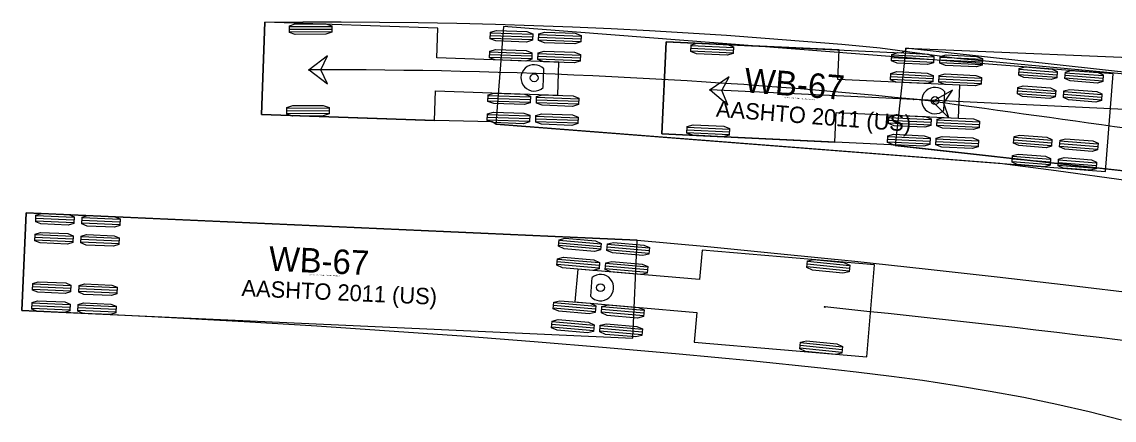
# Model space of a CAD drawing. Extents: x 2175591 to 2194071, y 76570 to 86955.
# Drawn here: x 2176268.4 to 2176363, y 77384.6 to 77419.1 of the extents above; entities that cross this region are included whole.
import ezdxf

# ---------------------------------------------------------------- set-up
doc = ezdxf.new("R2010")
doc.units = 0
doc.layers.add('C-UTIL-STRM-TEXT', color=7, linetype='Continuous')

msp = doc.modelspace()

# ---------------------------------------------------------------- linework, layer by layer
at = {"layer": 'C-UTIL-STRM-TEXT'}
for p, q in [((2176289.42, 77419.093), (2176289.135, 77411.098)), ((2176304.411, 77418.559), (2176289.42, 77419.093)), ((2176291.55, 77418.717), (2176295.216, 77418.727)), ((2176310.102, 77418.729), (2176309.442, 77410.254)), ((2176362.942, 77414.618), (2176310.102, 77418.729)), ((2176291.55, 77418.488), (2176295.217, 77418.498)), ((2176291.551, 77418.258), (2176295.218, 77418.269)), ((2176304.319, 77415.994), (2176304.411, 77418.559)), ((2176308.95, 77417.709), (2176312.614, 77417.579)), ((2176308.958, 77417.938), (2176312.623, 77417.808)), ((2176308.966, 77418.167), (2176312.631, 77418.037)), ((2176313.156, 77417.789), (2176316.82, 77417.658)), ((2176313.164, 77418.018), (2176316.828, 77417.887)), ((2176313.147, 77417.56), (2176316.812, 77417.429)), ((2176324.208, 77417.4), (2176323.829, 77409.409)), ((2176339.191, 77416.69), (2176324.208, 77417.4)), ((2176326.35, 77416.839), (2176330.013, 77416.666)), ((2176326.361, 77417.068), (2176330.024, 77416.895)), ((2176344.981, 77416.848), (2176344.04, 77408.4)), ((2176397.655, 77410.98), (2176344.981, 77416.848)), ((2176314.913, 77415.616), (2176304.319, 77415.994)), ((2176308.891, 77416.06), (2176312.556, 77415.93)), ((2176308.899, 77416.289), (2176312.564, 77416.159)), ((2176308.908, 77416.518), (2176312.572, 77416.388)), ((2176313.089, 77415.911), (2176316.753, 77415.78)), ((2176313.097, 77416.14), (2176316.761, 77416.009)), ((2176313.105, 77416.369), (2176316.769, 77416.238)), ((2176326.34, 77416.611), (2176330.002, 77416.437)), ((2176339.07, 77414.126), (2176339.191, 77416.69)), ((2176343.72, 77415.787), (2176347.383, 77415.613)), ((2176343.731, 77416.016), (2176347.393, 77415.842)), ((2176343.742, 77416.245), (2176347.404, 77416.071)), ((2176347.926, 77415.817), (2176351.589, 77415.643)), ((2176347.937, 77416.046), (2176351.6, 77415.872)), ((2176313.542, 77413.422), (2176313.599, 77415.038)), ((2176314.81, 77412.751), (2176314.913, 77415.616)), ((2176347.915, 77415.588), (2176351.578, 77415.415)), ((2176354.799, 77415.021), (2176358.089, 77414.765)), ((2176349.658, 77413.624), (2176339.07, 77414.126)), ((2176343.642, 77414.139), (2176347.305, 77413.965)), ((2176343.653, 77414.368), (2176347.315, 77414.194)), ((2176343.664, 77414.597), (2176347.326, 77414.423)), ((2176347.837, 77413.94), (2176351.5, 77413.766)), ((2176347.848, 77414.169), (2176351.511, 77413.995)), ((2176347.859, 77414.398), (2176351.522, 77414.224)), ((2176354.763, 77414.564), (2176358.053, 77414.308)), ((2176354.781, 77414.793), (2176358.071, 77414.537)), ((2176358.751, 77414.254), (2176362.041, 77413.998)), ((2176358.769, 77414.483), (2176362.059, 77414.227)), ((2176358.787, 77414.711), (2176362.077, 77414.455)), ((2176362.283, 77406.143), (2176362.942, 77414.618)), ((2176304.126, 77410.564), (2176304.217, 77413.129)), ((2176304.217, 77413.129), (2176314.81, 77412.751)), ((2176404.759, 77409.577), (2176328.014, 77413.215)), ((2176348.261, 77411.446), (2176348.338, 77413.061)), ((2176349.522, 77410.761), (2176349.658, 77413.624)), ((2176354.653, 77413.148), (2176357.943, 77412.892)), ((2176354.671, 77413.376), (2176357.961, 77413.12)), ((2176358.659, 77413.066), (2176361.949, 77412.81)), ((2176308.756, 77412.279), (2176312.421, 77412.149)), ((2176308.765, 77412.508), (2176312.429, 77412.378)), ((2176308.773, 77412.737), (2176312.437, 77412.607)), ((2176312.954, 77412.13), (2176316.618, 77411.999)), ((2176312.962, 77412.359), (2176316.626, 77412.228)), ((2176312.97, 77412.588), (2176316.634, 77412.457)), ((2176354.635, 77412.919), (2176357.925, 77412.663)), ((2176358.623, 77412.609), (2176361.913, 77412.353)), ((2176358.641, 77412.838), (2176361.931, 77412.582)), ((2176289.135, 77411.098), (2176304.126, 77410.564)), ((2176289.135, 77411.098), (2176289.135, 77411.098)), ((2176291.333, 77411.636), (2176295, 77411.649)), ((2176291.334, 77411.407), (2176295, 77411.42)), ((2176291.334, 77411.178), (2176295.001, 77411.191)), ((2176308.714, 77411.088), (2176312.378, 77410.958)), ((2176338.812, 77408.699), (2176338.934, 77411.263)), ((2176338.934, 77411.263), (2176349.522, 77410.761)), ((2176308.698, 77410.63), (2176312.362, 77410.5)), ((2176308.706, 77410.859), (2176312.37, 77410.729)), ((2176309.442, 77410.254), (2176362.283, 77406.143)), ((2176309.442, 77410.254), (2176309.442, 77410.254)), ((2176312.895, 77410.481), (2176316.559, 77410.35)), ((2176312.903, 77410.71), (2176316.568, 77410.579)), ((2176312.911, 77410.939), (2176316.576, 77410.808)), ((2176343.463, 77410.36), (2176347.125, 77410.186)), ((2176343.474, 77410.589), (2176347.136, 77410.415)), ((2176343.485, 77410.817), (2176347.147, 77410.644)), ((2176347.658, 77410.161), (2176351.321, 77409.987)), ((2176347.669, 77410.39), (2176351.332, 77410.216)), ((2176347.68, 77410.619), (2176351.342, 77410.445)), ((2176323.829, 77409.409), (2176338.812, 77408.699)), ((2176323.829, 77409.409), (2176323.829, 77409.409)), ((2176326.004, 77409.535), (2176329.667, 77409.362)), ((2176326.015, 77409.764), (2176329.678, 77409.59)), ((2176326.026, 77409.993), (2176329.689, 77409.819)), ((2176343.407, 77409.169), (2176347.069, 77408.996)), ((2176343.385, 77408.712), (2176347.047, 77408.538)), ((2176343.396, 77408.94), (2176347.058, 77408.767)), ((2176344.04, 77408.4), (2176396.714, 77402.532)), ((2176344.04, 77408.4), (2176344.04, 77408.4)), ((2176347.58, 77408.513), (2176351.243, 77408.339)), ((2176347.591, 77408.742), (2176351.254, 77408.568)), ((2176347.602, 77408.971), (2176351.264, 77408.797)), ((2176354.303, 77408.649), (2176357.593, 77408.393)), ((2176354.321, 77408.877), (2176357.611, 77408.621)), ((2176354.338, 77409.106), (2176357.629, 77408.85)), ((2176358.291, 77408.339), (2176361.581, 77408.083)), ((2176358.309, 77408.567), (2176361.599, 77408.311)), ((2176358.326, 77408.796), (2176361.616, 77408.54)), ((2176354.21, 77407.461), (2176357.501, 77407.205)), ((2176354.175, 77407.004), (2176357.465, 77406.748)), ((2176354.193, 77407.232), (2176357.483, 77406.976)), ((2176358.163, 77406.694), (2176361.453, 77406.438)), ((2176358.181, 77406.922), (2176361.471, 77406.666)), ((2176358.198, 77407.151), (2176361.488, 77406.895)), ((2176268.752, 77402.569), (2176268.369, 77394.078)), ((2176321.698, 77400.183), (2176268.752, 77402.569)), ((2176272.867, 77401.695), (2176269.57, 77401.844)), ((2176272.877, 77401.924), (2176269.58, 77402.073)), ((2176272.887, 77402.153), (2176269.591, 77402.302)), ((2176276.863, 77401.515), (2176273.566, 77401.664)), ((2176276.873, 77401.744), (2176273.576, 77401.893)), ((2176276.883, 77401.973), (2176273.587, 77402.122)), ((2176272.813, 77400.505), (2176269.516, 77400.654)), ((2176272.792, 77400.047), (2176269.496, 77400.196)), ((2176272.803, 77400.276), (2176269.506, 77400.425)), ((2176276.788, 77399.867), (2176273.492, 77400.016)), ((2176276.799, 77400.096), (2176273.502, 77400.244)), ((2176276.809, 77400.325), (2176273.512, 77400.473)), ((2176318.529, 77399.395), (2176314.876, 77399.711)), ((2176318.549, 77399.623), (2176314.896, 77399.939)), ((2176318.569, 77399.852), (2176314.916, 77400.167)), ((2176322.753, 77399.49), (2176319.1, 77399.806)), ((2176321.315, 77391.691), (2176321.698, 77400.183)), ((2176321.698, 77400.183), (2176321.698, 77400.183)), ((2176322.714, 77399.034), (2176319.061, 77399.349)), ((2176322.733, 77399.262), (2176319.08, 77399.577)), ((2176327.323, 77399.325), (2176327.102, 77396.768)), ((2176342.267, 77398.034), (2176327.323, 77399.325)), ((2176318.387, 77397.751), (2176314.734, 77398.067)), ((2176318.407, 77397.98), (2176314.754, 77398.295)), ((2176318.427, 77398.208), (2176314.774, 77398.524)), ((2176322.591, 77397.618), (2176318.938, 77397.934)), ((2176322.611, 77397.846), (2176318.958, 77398.162)), ((2176340.05, 77397.507), (2176336.402, 77397.879)), ((2176340.073, 77397.735), (2176336.426, 77398.107)), ((2176340.097, 77397.963), (2176336.449, 77398.335)), ((2176341.578, 77390.064), (2176342.267, 77398.034)), ((2176342.267, 77398.034), (2176342.267, 77398.034)), ((2176316.541, 77397.681), (2176316.294, 77394.825)), ((2176327.102, 77396.768), (2176316.541, 77397.681)), ((2176317.774, 77396.947), (2176317.635, 77395.336)), ((2176322.572, 77397.39), (2176318.919, 77397.705)), ((2176272.6, 77395.768), (2176269.303, 77395.917)), ((2176272.61, 77395.997), (2176269.313, 77396.146)), ((2176272.62, 77396.226), (2176269.324, 77396.375)), ((2176276.606, 77395.817), (2176273.309, 77395.965)), ((2176276.616, 77396.046), (2176273.319, 77396.194)), ((2176276.595, 77395.588), (2176273.299, 77395.737)), ((2176268.369, 77394.078), (2176321.315, 77391.691)), ((2176272.525, 77394.12), (2176269.229, 77394.268)), ((2176272.536, 77394.349), (2176269.239, 77394.497)), ((2176272.546, 77394.578), (2176269.249, 77394.726)), ((2176276.521, 77393.94), (2176273.225, 77394.088)), ((2176276.532, 77394.169), (2176273.235, 77394.317)), ((2176276.542, 77394.397), (2176273.245, 77394.546)), ((2176318.062, 77393.982), (2176314.408, 77394.298)), ((2176318.081, 77394.21), (2176314.428, 77394.526)), ((2176318.101, 77394.439), (2176314.448, 77394.754)), ((2176316.294, 77394.825), (2176326.855, 77393.912)), ((2176322.266, 77393.849), (2176318.613, 77394.164)), ((2176322.285, 77394.077), (2176318.632, 77394.393)), ((2176317.959, 77392.795), (2176314.306, 77393.11)), ((2176322.246, 77393.62), (2176318.593, 77393.936)), ((2176326.855, 77393.912), (2176326.634, 77391.355)), ((2176317.92, 77392.338), (2176314.266, 77392.654)), ((2176317.939, 77392.566), (2176314.286, 77392.882)), ((2176322.104, 77391.976), (2176318.451, 77392.292)), ((2176322.124, 77392.205), (2176318.471, 77392.52)), ((2176322.143, 77392.433), (2176318.49, 77392.749)), ((2176326.634, 77391.355), (2176341.578, 77390.064)), ((2176339.472, 77390.907), (2176335.825, 77391.28)), ((2176339.426, 77390.451), (2176335.778, 77390.824)), ((2176339.449, 77390.679), (2176335.802, 77391.052))]:
    msp.add_line(p, q, dxfattribs=at)
for points in [[(2176364.273, 77405.327), (2176358.005, 77406.213), (2176353.107, 77406.848), (2176309.442, 77410.254), (2176309.113, 77410.447), (2176304.162, 77410.563), (2176289.135, 77411.098), (2176289.42, 77419.093), (2176292.71, 77419.118), (2176296.036, 77419.121), (2176299.374, 77419.102), (2176302.716, 77419.062), (2176306.059, 77419), (2176309.403, 77418.915), (2176312.746, 77418.809), (2176316.087, 77418.681), (2176319.427, 77418.532), (2176322.766, 77418.36), (2176326.103, 77418.167), (2176329.438, 77417.952), (2176332.771, 77417.715), (2176336.101, 77417.456), (2176339.429, 77417.176), (2176342.753, 77416.87), (2176349.375, 77415.982), (2176388.741, 77412.312)], [(2176396.245, 77402.573), (2176344.068, 77408.397), (2176343.683, 77408.468), (2176323.829, 77409.409), (2176324.208, 77417.4), (2176344.556, 77416.436), (2176344.959, 77416.646), (2176344.981, 77416.848), (2176369.887, 77415.788)], [(2176347.273, 77412.211), (2176346.943, 77412.256), (2176346.612, 77412.298), (2176346.281, 77412.338), (2176345.95, 77412.375), (2176345.619, 77412.41)], [(2176363.653, 77384.577), (2176360.865, 77385.291), (2176358.039, 77385.943), (2176355.18, 77386.537), (2176352.289, 77387.077), (2176349.364, 77387.567), (2176346.421, 77388.009), (2176343.716, 77388.376), (2176340.661, 77388.752), (2176337.615, 77389.094), (2176331.52, 77389.71), (2176325.313, 77390.291), (2176319.039, 77390.845), (2176312.762, 77391.365), (2176306.482, 77391.852), (2176300.201, 77392.305), (2176293.917, 77392.724), (2176287.631, 77393.109), (2176281.343, 77393.459), (2176275.049, 77393.774), (2176268.369, 77394.078), (2176268.752, 77402.569), (2176268.765, 77402.568), (2176268.765, 77402.568)], [(2176268.765, 77402.568), (2176321.698, 77400.183), (2176327.788, 77399.625), (2176334.149, 77399.011), (2176340.559, 77398.36), (2176346.64, 77397.711), (2176352.869, 77397.016), (2176359.09, 77396.29), (2176365.35, 77395.528)]]:
    msp.add_lwpolyline(points, dxfattribs=at)
for points in [[(2176291.551, 77418.202), (2176291.55, 77418.774), (2176292.062, 77418.947), (2176294.702, 77418.955), (2176295.216, 77418.784), (2176295.218, 77418.212), (2176294.705, 77418.038), (2176292.065, 77418.031)], [(2176308.948, 77417.652), (2176308.968, 77418.224), (2176309.488, 77418.378), (2176312.126, 77418.284), (2176312.633, 77418.093), (2176312.612, 77417.522), (2176312.093, 77417.368), (2176309.455, 77417.462)], [(2176313.145, 77417.503), (2176313.166, 77418.074), (2176313.685, 77418.228), (2176316.323, 77418.134), (2176316.83, 77417.944), (2176316.81, 77417.372), (2176316.291, 77417.218), (2176313.652, 77417.312)], [(2176308.889, 77416.003), (2176308.91, 77416.575), (2176309.429, 77416.729), (2176312.067, 77416.635), (2176312.574, 77416.444), (2176312.554, 77415.873), (2176312.034, 77415.719), (2176309.396, 77415.813)], [(2176326.337, 77416.554), (2176326.364, 77417.125), (2176326.885, 77417.273), (2176329.522, 77417.148), (2176330.027, 77416.952), (2176329.999, 77416.38), (2176329.479, 77416.232), (2176326.842, 77416.357)], [(2176293.275, 77414.953), (2176294.866, 77413.741), (2176294.275, 77414.956), (2176294.858, 77416.176)], [(2176313.087, 77415.854), (2176313.107, 77416.425), (2176313.626, 77416.579), (2176316.264, 77416.485), (2176316.771, 77416.295), (2176316.751, 77415.723), (2176316.232, 77415.569), (2176313.593, 77415.663)], [(2176343.717, 77415.73), (2176343.744, 77416.301), (2176344.265, 77416.449), (2176346.902, 77416.324), (2176347.407, 77416.128), (2176347.38, 77415.557), (2176346.859, 77415.409), (2176344.222, 77415.534)], [(2176347.913, 77415.531), (2176347.94, 77416.103), (2176348.461, 77416.251), (2176351.098, 77416.126), (2176351.602, 77415.929), (2176351.575, 77415.358), (2176351.054, 77415.21), (2176348.417, 77415.335)], [(2176354.759, 77414.508), (2176354.803, 77415.078), (2176355.277, 77415.214), (2176357.646, 77415.03), (2176358.093, 77414.822), (2176358.049, 77414.252), (2176357.575, 77414.116), (2176355.206, 77414.3)], [(2176358.747, 77414.197), (2176358.791, 77414.768), (2176359.265, 77414.904), (2176361.634, 77414.719), (2176362.081, 77414.512), (2176362.037, 77413.942), (2176361.563, 77413.806), (2176359.194, 77413.99)], [(2176328.014, 77413.215), (2176329.541, 77411.924), (2176329.013, 77413.168), (2176329.657, 77414.356)], [(2176343.639, 77414.082), (2176343.666, 77414.653), (2176344.187, 77414.801), (2176346.824, 77414.676), (2176347.329, 77414.48), (2176347.302, 77413.908), (2176346.781, 77413.761), (2176344.144, 77413.886)], [(2176347.835, 77413.883), (2176347.862, 77414.455), (2176348.383, 77414.602), (2176351.02, 77414.477), (2176351.524, 77414.281), (2176351.497, 77413.71), (2176350.976, 77413.562), (2176348.339, 77413.687)], [(2176308.754, 77412.222), (2176308.775, 77412.794), (2176309.294, 77412.948), (2176311.932, 77412.854), (2176312.439, 77412.664), (2176312.419, 77412.092), (2176311.9, 77411.938), (2176309.261, 77412.032)], [(2176347.273, 77412.211), (2176348.681, 77410.79), (2176348.264, 77412.075), (2176349.01, 77413.203)], [(2176354.631, 77412.863), (2176354.675, 77413.433), (2176355.149, 77413.569), (2176357.518, 77413.385), (2176357.965, 77413.177), (2176357.921, 77412.607), (2176357.447, 77412.471), (2176355.078, 77412.655)], [(2176358.619, 77412.552), (2176358.663, 77413.123), (2176359.137, 77413.259), (2176361.506, 77413.074), (2176361.953, 77412.867), (2176361.909, 77412.297), (2176361.435, 77412.161), (2176359.066, 77412.345)], [(2176312.952, 77412.073), (2176312.972, 77412.645), (2176313.491, 77412.798), (2176316.13, 77412.704), (2176316.637, 77412.514), (2176316.616, 77411.942), (2176316.097, 77411.788), (2176313.459, 77411.882)], [(2176291.335, 77411.121), (2176291.333, 77411.693), (2176291.845, 77411.867), (2176294.485, 77411.876), (2176294.999, 77411.706), (2176295.001, 77411.134), (2176294.489, 77410.96), (2176291.849, 77410.951)], [(2176308.696, 77410.574), (2176308.716, 77411.145), (2176309.235, 77411.299), (2176311.874, 77411.205), (2176312.38, 77411.015), (2176312.36, 77410.443), (2176311.841, 77410.289), (2176309.203, 77410.383)], [(2176312.893, 77410.424), (2176312.913, 77410.996), (2176313.433, 77411.15), (2176316.071, 77411.055), (2176316.578, 77410.865), (2176316.557, 77410.293), (2176316.038, 77410.139), (2176313.4, 77410.233)], [(2176326.002, 77409.478), (2176326.029, 77410.05), (2176326.55, 77410.198), (2176329.187, 77410.073), (2176329.691, 77409.876), (2176329.664, 77409.305), (2176329.143, 77409.157), (2176326.506, 77409.282)], [(2176343.46, 77410.303), (2176343.487, 77410.874), (2176344.008, 77411.022), (2176346.645, 77410.897), (2176347.15, 77410.701), (2176347.123, 77410.129), (2176346.602, 77409.981), (2176343.965, 77410.106)], [(2176347.656, 77410.104), (2176347.683, 77410.675), (2176348.203, 77410.823), (2176350.841, 77410.698), (2176351.345, 77410.502), (2176351.318, 77409.931), (2176350.797, 77409.783), (2176348.16, 77409.908)], [(2176343.382, 77408.655), (2176343.409, 77409.226), (2176343.93, 77409.374), (2176346.567, 77409.249), (2176347.072, 77409.053), (2176347.045, 77408.481), (2176346.524, 77408.333), (2176343.887, 77408.458)], [(2176347.577, 77408.456), (2176347.604, 77409.027), (2176348.125, 77409.175), (2176350.762, 77409.05), (2176351.267, 77408.854), (2176351.24, 77408.282), (2176350.719, 77408.135), (2176348.082, 77408.259)], [(2176354.298, 77408.592), (2176354.343, 77409.163), (2176354.817, 77409.299), (2176357.186, 77409.114), (2176357.633, 77408.907), (2176357.589, 77408.336), (2176357.115, 77408.2), (2176354.746, 77408.385)], [(2176358.286, 77408.282), (2176358.331, 77408.852), (2176358.805, 77408.988), (2176361.174, 77408.804), (2176361.621, 77408.596), (2176361.577, 77408.026), (2176361.103, 77407.89), (2176358.734, 77408.074)], [(2176354.171, 77406.947), (2176354.215, 77407.518), (2176354.689, 77407.654), (2176357.058, 77407.469), (2176357.505, 77407.262), (2176357.461, 77406.691), (2176356.987, 77406.555), (2176354.618, 77406.74)], [(2176358.158, 77406.637), (2176358.203, 77407.207), (2176358.677, 77407.343), (2176361.046, 77407.159), (2176361.493, 77406.951), (2176361.449, 77406.381), (2176360.975, 77406.245), (2176358.606, 77406.429)], [(2176272.89, 77402.21), (2176272.864, 77401.639), (2176272.395, 77401.487), (2176270.021, 77401.594), (2176269.568, 77401.787), (2176269.593, 77402.359), (2176270.063, 77402.51), (2176272.436, 77402.403)], [(2176276.886, 77402.03), (2176276.86, 77401.458), (2176276.391, 77401.307), (2176274.017, 77401.414), (2176273.563, 77401.607), (2176273.589, 77402.178), (2176274.058, 77402.33), (2176276.432, 77402.223)], [(2176272.816, 77400.562), (2176272.79, 77399.99), (2176272.321, 77399.839), (2176269.947, 77399.946), (2176269.493, 77400.139), (2176269.519, 77400.71), (2176269.988, 77400.862), (2176272.362, 77400.755)], [(2176276.812, 77400.382), (2176276.786, 77399.81), (2176276.317, 77399.659), (2176273.943, 77399.766), (2176273.489, 77399.959), (2176273.515, 77400.53), (2176273.984, 77400.682), (2176276.358, 77400.575)], [(2176318.574, 77399.908), (2176318.524, 77399.338), (2176317.998, 77399.211), (2176315.368, 77399.438), (2176314.871, 77399.654), (2176314.921, 77400.224), (2176315.447, 77400.351), (2176318.077, 77400.124)], [(2176322.758, 77399.547), (2176322.709, 77398.977), (2176322.183, 77398.849), (2176319.552, 77399.077), (2176319.056, 77399.293), (2176319.105, 77399.862), (2176319.631, 77399.99), (2176322.261, 77399.763)], [(2176318.432, 77398.264), (2176318.382, 77397.695), (2176317.856, 77397.567), (2176315.226, 77397.794), (2176314.729, 77398.01), (2176314.779, 77398.58), (2176315.305, 77398.708), (2176317.935, 77398.48)], [(2176322.616, 77397.903), (2176322.567, 77397.333), (2176322.04, 77397.206), (2176319.41, 77397.433), (2176318.914, 77397.649), (2176318.963, 77398.219), (2176319.489, 77398.346), (2176322.119, 77398.119)], [(2176340.102, 77398.019), (2176340.044, 77397.45), (2176339.516, 77397.331), (2176336.89, 77397.599), (2176336.397, 77397.823), (2176336.455, 77398.392), (2176336.983, 77398.511), (2176339.609, 77398.243)], [(2176272.623, 77396.283), (2176272.597, 77395.711), (2176272.128, 77395.56), (2176269.754, 77395.667), (2176269.3, 77395.86), (2176269.326, 77396.431), (2176269.795, 77396.583), (2176272.169, 77396.476)], [(2176276.619, 77396.103), (2176276.593, 77395.531), (2176276.124, 77395.38), (2176273.75, 77395.487), (2176273.296, 77395.68), (2176273.322, 77396.251), (2176273.791, 77396.403), (2176276.165, 77396.296)], [(2176272.548, 77394.634), (2176272.523, 77394.063), (2176272.053, 77393.912), (2176269.68, 77394.019), (2176269.226, 77394.212), (2176269.252, 77394.783), (2176269.721, 77394.934), (2176272.095, 77394.827)], [(2176276.544, 77394.454), (2176276.519, 77393.883), (2176276.049, 77393.731), (2176273.676, 77393.838), (2176273.222, 77394.031), (2176273.248, 77394.603), (2176273.717, 77394.754), (2176276.091, 77394.647)], [(2176318.106, 77394.495), (2176318.057, 77393.925), (2176317.53, 77393.798), (2176314.9, 77394.025), (2176314.404, 77394.241), (2176314.453, 77394.811), (2176314.979, 77394.938), (2176317.609, 77394.711)], [(2176322.29, 77394.134), (2176322.241, 77393.564), (2176321.715, 77393.436), (2176319.085, 77393.664), (2176318.588, 77393.879), (2176318.637, 77394.449), (2176319.164, 77394.577), (2176321.794, 77394.349)], [(2176317.964, 77392.851), (2176317.915, 77392.281), (2176317.388, 77392.154), (2176314.758, 77392.381), (2176314.262, 77392.597), (2176314.311, 77393.167), (2176314.837, 77393.294), (2176317.467, 77393.067)], [(2176322.148, 77392.49), (2176322.099, 77391.92), (2176321.573, 77391.792), (2176318.943, 77392.02), (2176318.446, 77392.236), (2176318.495, 77392.805), (2176319.021, 77392.933), (2176321.652, 77392.706)], [(2176339.478, 77390.963), (2176339.42, 77390.394), (2176338.892, 77390.275), (2176336.266, 77390.544), (2176335.772, 77390.767), (2176335.831, 77391.336), (2176336.359, 77391.456), (2176338.985, 77391.187)]]:
    msp.add_lwpolyline(points, close=True, dxfattribs=at)
for centre, radius in [((2176293.275, 77414.953), 0.0417), ((2176312.763, 77414.259), 0.34), ((2176328.014, 77413.215), 0.0417), ((2176345.619, 77412.41), 0.0417), ((2176345.619, 77412.41), 0.0417), ((2176347.492, 77412.292), 0.34), ((2176347.273, 77412.211), 0.0417), ((2176347.273, 77412.211), 0.0417), ((2176318.51, 77396.072), 0.34), ((2176337.937, 77394.393), 0.0417)]:
    msp.add_circle(centre, radius, dxfattribs=at)
for centre, radius, start, end in [((2176294.869, 76907.8), 507.156, 84.25702, 90.18009), ((2176312.763, 77414.259), 1.143, 42.95894, 312.95894), ((2176347.492, 77412.292), 1.143, 42.28697, 312.28697), ((2175794.378, 73359.163), 4090.586, 81.212179, 82.231966), ((2176318.51, 77396.072), 1.143, 220.06142, 130.06142), ((2176211.189, 76154.058), 1246.794, 81.459368, 84.165269)]:
    msp.add_arc(centre, radius, start, end, dxfattribs=at)

# ---------------------------------------------------------------- texts
for s, height, rotation, p in [('WB-67', 2.125, 355.55147, (2176330.909, 77413.017)), ('AASHTO 2011 (US)', 1.41667, 355.55147, (2176328.485, 77410.897)), ('(c) 2019 Transoft Solutions, Inc. All rights reserved.', 0.085, 355.55147, (2176334.462, 77412.528)), ('WB-67', 2.125, 357.41919, (2176289.734, 77397.539)), ('(c) 2019 Transoft Solutions, Inc. All rights reserved.', 0.085, 357.41919, (2176293.301, 77397.166)), ('AASHTO 2011 (US)', 1.41667, 357.41919, (2176287.381, 77395.341))]:
    msp.add_text(s, height=height, rotation=rotation, dxfattribs=at).set_placement(p)

doc.saveas('drawing.dxf')
